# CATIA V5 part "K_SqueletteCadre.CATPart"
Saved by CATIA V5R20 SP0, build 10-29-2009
Part number: Squelette_Cadre
Bounding box of the stored display mesh (mm): x 29.843 to 202.731, y -789.584 to -56.23, z -511.763 to -50
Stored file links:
  G:\Khaled_CFAO_2011\ST2M\ST2M_GR1\bmartinez\Khaled\CAD_ThinkMOTION\K_SqueletteCadre.CATPart
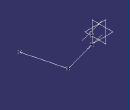
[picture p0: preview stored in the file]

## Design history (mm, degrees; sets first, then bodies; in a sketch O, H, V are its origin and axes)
Set1
  Point1: type OnPlane, Support Plane1, RefPoint Point2, H 0, V -50, Direction (-0.9686, -0.2487, 0)
  Plane1: stored without definition
  Point2: stored without definition
  Point3: type OnPlane, Support Plane2, RefPoint Point4, H 0, V -150, Direction (-0.9686, -0.2487, 0)
  Plane2: stored without definition
  Point4: stored without definition
  Line1: type PtPt, FirstPoint Point1, SecondPoint Point3
  Plane3: type Angle, RefPlane Plane4, Direction Line2, Angle -35
  Line2: stored without definition
  Plane4: stored without definition
  Plane5: type OffsetPt, RefPlane Plane3, RefPoint Point3
  Point5: type OnPlane, Support Plane5, H 0, V -600, Direction (-0.9686, -0.2487, 0)
  Line3: type PtPt, FirstPoint Point3, SecondPoint Point5
  Line4: type PtDir, RefPoint Point5, Direction Plane6, Start 0, End 500
  Plane6: stored without definition
  Point6: type OnCurve, Support Line4, Length 0
Body1 (main body)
